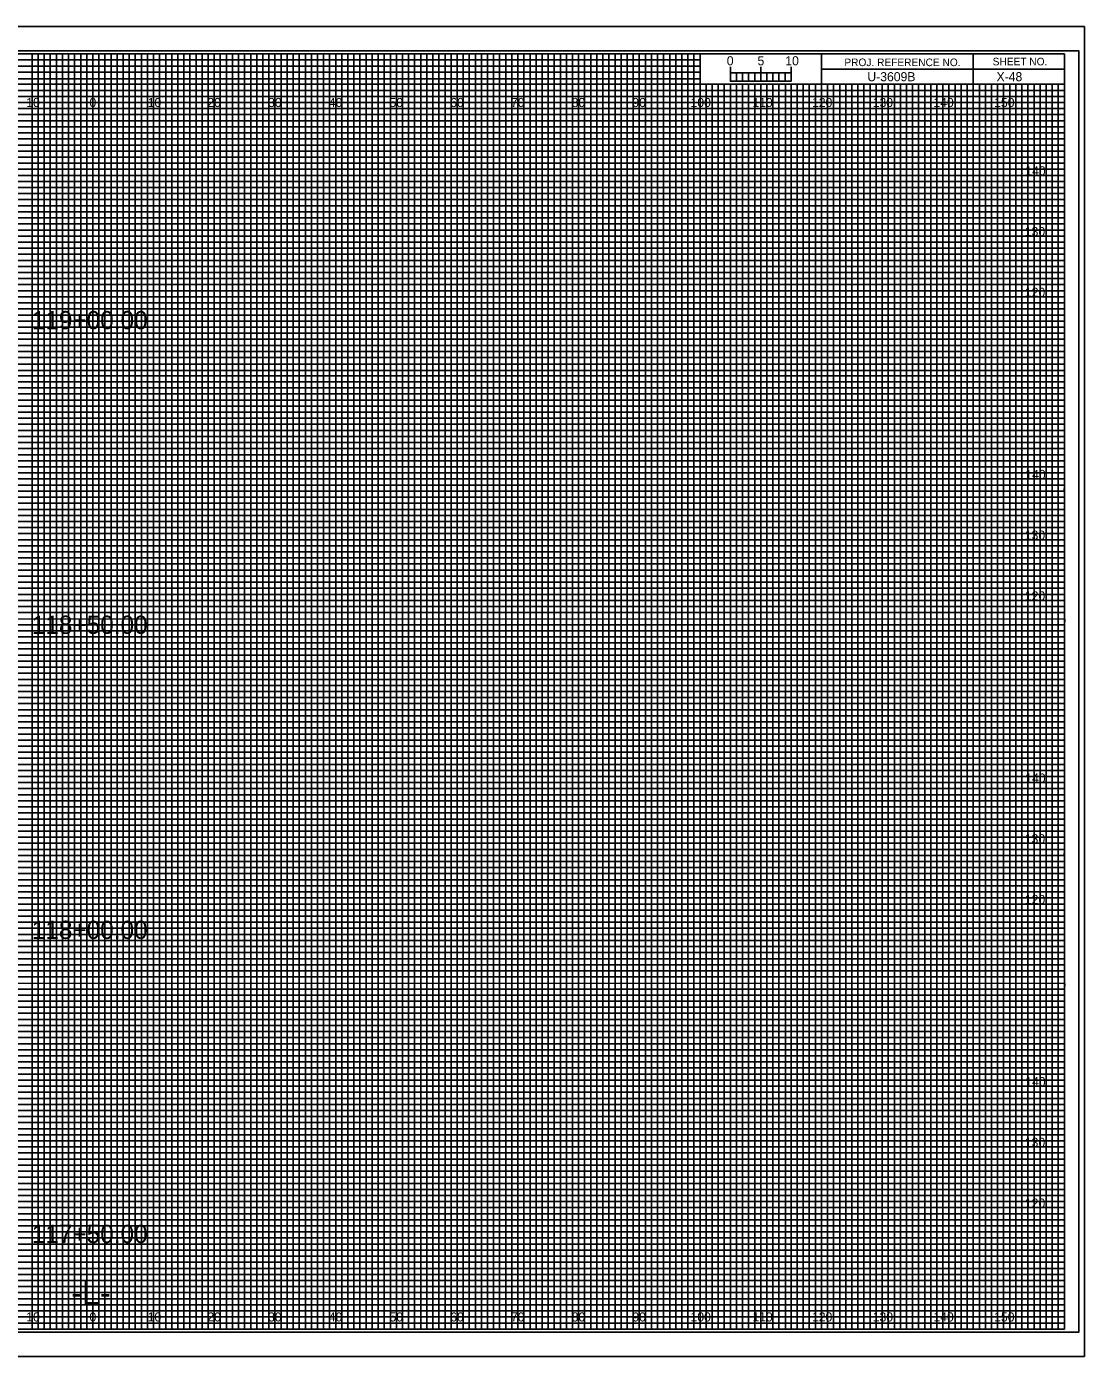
# Model space of a CAD drawing. Extents: x -13 to 329, y -17 to 10994.
# Drawn here: x 149.1 to 323.3, y 10115.5 to 10334.5 of the extents above; entities that cross this region are included whole.
import ezdxf

# ---------------------------------------------------------------- set-up
doc = ezdxf.new("R2010")
doc.units = 0
for name, color, linetype in [('Prop XS Alignment Label', 7, 'Continuous'), ('Prop XS Bar Scale Labels', 7, 'Continuous'), ('Prop XS Elevation Labels', 7, 'Continuous'), ('Prop XS Offset Labels', 7, 'Continuous'), ('Prop XS Project Number', 7, 'Continuous'), ('Prop XS Sheet Number', 7, 'Continuous'), ('Prop XS Station Labels', 7, 'Continuous'), ('Sheet Cross Section CELL', 7, 'Continuous'), ('Sheet Cross Section Grid Major CELL', 7, 'Continuous'), ('Sheet Cross Section Grid Middle CELL', 7, 'Continuous'), ('Sheet Cross Section Grid Minor 1 CELL', 7, 'Continuous'), ('Sheet Cross Section Grid Minor 2 CELL', 7, 'Continuous'), ('Sheet Cross Section Scale CELL', 7, 'Continuous'), ('Sheet Cutting Line CELL', 7, 'Continuous'), ('Sheet DOT Grid CELL', 7, 'Continuous'), ('Sheet Plot Border Inside CELL', 7, 'Continuous'), ('Sheet Plot Border Outside CELL', 7, 'Continuous')]:
    doc.layers.add(name, color=color, linetype=linetype)

msp = doc.modelspace()

# ---------------------------------------------------------------- linework, layer by layer
at = {"layer": 'Sheet Cross Section CELL'}
for p, q in [((305, 10330), (305, 10325)), ((305, 10325), (305, 10330)), ((280, 10327.5), (280, 10325)), ((320, 10327.49), (280, 10327.49)), ((280, 10325), (320, 10325))]:
    msp.add_line(p, q, dxfattribs=at)
for points in [[(320, 10330), (0, 10330), (0, 10120), (320, 10120)], [(280, 10330), (260, 10330), (260, 10325.03), (280, 10325.03)], [(320, 10330), (280, 10330), (280, 10325), (320, 10325)]]:
    msp.add_lwpolyline(points, close=True, dxfattribs=at)
at = {"layer": 'Sheet Cross Section Grid Major CELL'}
for p, q in [((150, 10330), (140, 10330)), ((150, 10120), (150, 10330)), ((170, 10330), (160, 10330)), ((160, 10330), (160, 10120)), ((170, 10120), (170, 10330)), ((190, 10330), (180, 10330)), ((180, 10330), (180, 10120)), ((190, 10120), (190, 10330)), ((210, 10330), (200, 10330)), ((200, 10330), (200, 10120)), ((210, 10120), (210, 10330)), ((230, 10330), (220, 10330)), ((220, 10330), (220, 10120)), ((230, 10120), (230, 10330)), ((250, 10330), (240, 10330)), ((240, 10330), (240, 10120)), ((250, 10120), (250, 10330)), ((260, 10330), (260, 10120)), ((270, 10120), (270, 10325)), ((290, 10325), (280, 10325)), ((280, 10325), (280, 10120)), ((290, 10120), (290, 10325)), ((310, 10325), (300, 10325)), ((300, 10325), (300, 10120)), ((310, 10120), (310, 10325)), ((160, 10120), (150, 10120)), ((180, 10120), (170, 10120)), ((200, 10120), (190, 10120)), ((220, 10120), (210, 10120)), ((240, 10120), (230, 10120)), ((260, 10120), (250, 10120)), ((280, 10120), (270, 10120)), ((300, 10120), (290, 10120)), ((320, 10120), (310, 10120)), ((320, 10120), (320, 10120))]:
    msp.add_line(p, q, dxfattribs=at)
for points in [[(0, 10320), (320, 10320), (320, 10310), (0, 10310)], [(0, 10300), (320, 10300), (320, 10290), (0, 10290)], [(0, 10280), (320, 10280), (320, 10270), (0, 10270)], [(0, 10260), (320, 10260), (320, 10250), (0, 10250)], [(0, 10240), (320, 10240), (320, 10230), (0, 10230)], [(0, 10220), (320, 10220), (320, 10210), (0, 10210)], [(0, 10200), (320, 10200), (320, 10190), (0, 10190)], [(0, 10180), (320, 10180), (320, 10170), (0, 10170)], [(0, 10160), (320, 10160), (320, 10150), (0, 10150)], [(0, 10140), (320, 10140), (320, 10130), (0, 10130)]]:
    msp.add_lwpolyline(points, dxfattribs=at)
at = {"layer": 'Sheet Cross Section Grid Middle CELL'}
for points in [[(145, 10120), (155, 10120), (155, 10330), (165, 10330), (165, 10120), (175, 10120), (175, 10330), (185, 10330), (185, 10120), (195, 10120), (195, 10330), (205, 10330), (205, 10120), (215, 10120), (215, 10330), (225, 10330), (225, 10120), (235, 10120), (235, 10330), (245, 10330), (245, 10120), (255, 10120), (255, 10330), (259.93, 10330), (260, 10330), (260, 10325), (264.99, 10325), (264.99, 10120), (275, 10120), (275, 10325), (285, 10325), (285, 10120), (295, 10120), (295, 10325), (305, 10325), (305, 10120), (315, 10120), (315, 10325)], [(0, 10325), (275, 10325)], [(0, 10305), (320, 10305), (320, 10315), (0, 10315)], [(0, 10285), (320, 10285), (320, 10295), (0, 10295)], [(0, 10265), (320, 10265), (320, 10275), (0, 10275)], [(0, 10245), (320, 10245), (320, 10255), (0, 10255)], [(0, 10225), (320, 10225), (320, 10235), (0, 10235)], [(0, 10205), (320, 10205), (320, 10215), (0, 10215)], [(0, 10185), (320, 10185), (320, 10195), (0, 10195)], [(0, 10165), (320, 10165), (320, 10175), (0, 10175)], [(0, 10145), (320, 10145), (320, 10155), (0, 10155)], [(0, 10125), (320, 10125), (320, 10135), (0, 10135)]]:
    msp.add_lwpolyline(points, dxfattribs=at)
at = {"layer": 'Sheet Cross Section Grid Minor 1 CELL'}
for p, q in [((0, 10329), (260, 10329)), ((260, 10329), (260, 10327.98)), ((260, 10327.98), (0, 10327.98)), ((0, 10327), (260, 10327)), ((260, 10325.89), (0, 10325.89)), ((260, 10327), (260, 10325.89)), ((0, 10324), (320, 10324))]:
    msp.add_line(p, q, dxfattribs=at)
for points in [[(0, 10323), (270, 10323), (320, 10323), (320, 10322), (0, 10322)], [(0, 10321), (320, 10321), (320, 10319), (0, 10319)], [(0, 10318), (320, 10318), (320, 10317), (0, 10316.98)], [(0, 10316), (320, 10316), (320, 10314), (0, 10314)], [(0, 10313), (320, 10313), (320, 10312), (0, 10312)], [(0, 10311), (320, 10311), (320, 10309), (0, 10309)], [(0, 10308), (320, 10308), (320, 10307), (0, 10307)], [(0, 10306), (320, 10306), (320, 10304), (0, 10304)], [(0, 10303), (320, 10303), (320, 10302), (0, 10302)], [(0, 10301), (320, 10301), (320, 10299), (0, 10299)], [(0, 10298), (320, 10298), (320, 10297), (0, 10297)], [(0, 10296), (320, 10296), (320, 10293.95), (320, 10293), (320, 10292), (0, 10292)], [(0, 10294), (320, 10294), (320, 10293), (0, 10293)], [(0, 10291), (320, 10291), (320, 10289), (0, 10289.03)], [(0, 10289.03), (320, 10289), (320, 10288), (0, 10288)], [(0, 10287), (320, 10287), (320, 10286), (0, 10286)], [(0, 10284), (320, 10284), (320, 10283), (0, 10283)], [(0, 10282), (320, 10282), (320, 10281), (0, 10281)], [(-0.07, 10278.89), (320, 10278.89), (320, 10277.88), (-0.07, 10277.88)], [(0, 10277), (320, 10277), (320, 10276), (0, 10276)], [(0, 10274), (320, 10274), (320, 10273), (0, 10273)], [(0, 10272), (320, 10272), (320, 10271), (0, 10271)], [(0, 10269), (320, 10269), (320, 10268), (0, 10268)], [(0, 10267), (320, 10267), (320, 10266), (0, 10266)], [(0, 10264), (320, 10264), (320, 10263), (0, 10263)], [(0, 10262), (320, 10262), (320, 10261), (0, 10261)], [(0, 10259), (320, 10259), (319.99, 10257.98), (0, 10258)], [(0, 10257), (320, 10257), (320, 10256), (0, 10256)], [(0, 10254), (320, 10254), (320, 10253), (0, 10253)], [(0, 10252), (320, 10252), (320, 10251), (0, 10251)], [(0, 10249), (320, 10249), (320, 10248), (0, 10248)], [(0, 10247), (320, 10247), (320, 10246), (0, 10246)], [(0, 10244), (320, 10244), (320, 10243), (0, 10243)], [(0, 10242), (320, 10242), (320, 10241), (0, 10241)], [(0, 10239), (320, 10239), (320, 10238), (0, 10238)], [(0, 10236.99), (320.07, 10236.91), (320, 10236), (0, 10236)], [(0, 10234), (320, 10234), (320, 10233), (0, 10233)], [(0, 10232), (320, 10232), (320, 10231), (0, 10231)], [(0, 10229), (320, 10229), (320, 10228), (0, 10228)], [(0, 10227), (320, 10227), (320, 10226), (0, 10226)], [(0, 10224), (320, 10224), (320, 10223), (0, 10223)], [(0, 10222), (320, 10222), (320, 10221), (0, 10221)], [(0, 10219), (320, 10219), (320, 10218), (0, 10218)], [(0, 10217), (320, 10217), (320, 10216), (0, 10216)], [(0, 10214), (320, 10214), (320, 10213), (0, 10213)], [(0, 10212), (320, 10212), (320, 10211), (0, 10211)], [(0, 10209), (320, 10209), (320, 10208), (0, 10208)], [(0, 10207), (320, 10207), (320, 10206), (0, 10206)], [(0, 10204), (320, 10204), (320, 10203), (0, 10203)], [(0, 10202), (320, 10202), (320, 10201), (0, 10201)], [(0, 10199), (320, 10199), (319.99, 10197.98), (0, 10198)], [(0, 10197), (320, 10197), (320, 10196), (0, 10196)], [(0, 10194), (320, 10194), (320, 10193), (0, 10193)], [(0, 10192), (320, 10192), (320, 10191), (0, 10191)], [(0, 10189), (320, 10189), (320, 10188), (0, 10188)], [(0, 10187), (320, 10187), (320, 10186), (0, 10186)], [(0, 10184), (320, 10184), (320, 10183), (0, 10183)], [(0, 10182), (320, 10182), (320, 10181), (0, 10181)], [(0, 10179), (320, 10179), (320, 10178), (0, 10178)], [(0, 10176.99), (320.07, 10176.91), (320, 10176), (0, 10176)], [(0, 10174), (320, 10174), (320, 10173), (0, 10173)], [(0, 10172), (320, 10172), (320, 10171), (0, 10171)], [(0, 10169), (320, 10169), (320, 10168), (0, 10168)], [(0, 10167), (320, 10167), (320, 10166), (0, 10166)], [(0, 10164), (320, 10164), (320, 10163), (0, 10163)], [(0, 10162), (320, 10162), (320, 10161), (0, 10161)], [(0, 10159), (320, 10159), (320, 10158), (0, 10158)], [(0, 10157), (320, 10157), (320, 10156), (0, 10156)], [(0, 10154), (320, 10154), (320, 10153), (0, 10153)], [(0, 10152), (320, 10152), (320, 10151), (0, 10151)], [(0, 10149), (320, 10149), (320, 10148), (0, 10148)], [(0, 10147), (320, 10147), (320, 10146), (0, 10146)], [(0, 10144), (320, 10144), (320, 10143), (0, 10143)], [(0, 10142), (320, 10142), (320, 10141), (0, 10141)], [(0, 10139), (320, 10139), (320, 10138), (0, 10138)], [(0, 10137), (320, 10137), (320, 10136), (0, 10136)], [(0, 10134), (320, 10134), (320, 10133), (0, 10133)], [(0, 10132), (320, 10132), (320, 10131), (0, 10131)], [(0, 10129), (320, 10129), (320, 10128), (0, 10128)], [(0, 10127), (320, 10127), (320, 10126), (0, 10126)], [(0, 10124), (320, 10124), (320, 10123), (0, 10123)], [(0, 10122), (320, 10122), (320, 10121), (0, 10121)]]:
    msp.add_lwpolyline(points, dxfattribs=at)
at = {"layer": 'Sheet Cross Section Grid Minor 2 CELL'}
for p, q in [((267, 10325), (266.01, 10325)), ((266.01, 10325), (266.01, 10120)), ((267, 10120), (267, 10325)), ((269, 10325), (268, 10325)), ((268, 10325), (268, 10120)), ((269, 10120), (269, 10325)), ((266.01, 10120), (265, 10120)), ((268, 10120), (267, 10120))]:
    msp.add_line(p, q, dxfattribs=at)
for points in [[(150, 10120), (151, 10120), (151, 10330), (152, 10330), (152, 10120)], [(152, 10120), (153, 10120), (153, 10330), (154, 10330), (154, 10120)], [(155, 10120), (156, 10120), (156, 10330), (157, 10330), (157, 10120)], [(157, 10120), (158, 10120), (158, 10330), (159, 10330), (159, 10120)], [(160, 10120), (161, 10120), (161, 10330), (162, 10330), (162, 10120)], [(162, 10120), (163, 10120), (163, 10330), (164, 10330), (164, 10120)], [(165, 10120), (166, 10120), (166, 10330), (167, 10330), (167, 10120)], [(167, 10120), (168, 10120), (168, 10330), (169, 10330), (169, 10120)], [(170, 10120), (171, 10120), (171, 10330), (172, 10330), (172, 10120)], [(172, 10120), (173, 10120), (173, 10330), (174, 10330), (174, 10120)], [(175, 10120), (176, 10120), (176, 10330), (177, 10330), (177, 10120)], [(177, 10120), (178, 10120), (178, 10330), (179, 10330), (179, 10120)], [(180, 10120), (181, 10120), (181, 10330), (182, 10330), (182, 10120)], [(182, 10120), (183, 10120), (183, 10330), (184, 10330), (184, 10120)], [(185, 10120), (186, 10120), (186, 10330), (187, 10330), (187, 10120)], [(187, 10120), (188, 10120), (188, 10330), (189, 10330), (189, 10120)], [(190, 10120), (191, 10120), (191, 10330), (192, 10330), (192, 10120)], [(192, 10120), (193, 10120), (193, 10330), (194, 10330), (194, 10120)], [(195, 10120), (196, 10120), (196, 10330), (197, 10330), (197, 10120)], [(197, 10120), (198, 10120), (198, 10330), (199, 10330), (199, 10120)], [(200, 10120), (201, 10120), (201, 10330), (202, 10330), (202, 10120)], [(202, 10120), (203, 10120), (203, 10330), (204, 10330), (204, 10120)], [(205, 10120), (206, 10120), (206, 10330), (207, 10330), (207, 10120)], [(207, 10120), (208, 10120), (208, 10330), (209, 10330), (209, 10120)], [(210, 10120), (211, 10120), (211, 10330), (212, 10330), (212, 10120)], [(212, 10120), (213, 10120), (213, 10330), (214, 10330), (214, 10120)], [(215, 10120), (216, 10120), (216, 10330), (217, 10330), (217, 10120)], [(217, 10120), (218, 10120), (218, 10330), (219, 10330), (219, 10120)], [(220, 10120), (221, 10120), (221, 10330), (222, 10330), (222, 10120)], [(222, 10120), (223, 10120), (223, 10330), (224, 10330), (224, 10120)], [(225, 10120), (226, 10120), (226, 10330), (227, 10330), (227, 10120)], [(227, 10120), (228, 10120), (228, 10330), (229, 10330), (229, 10120)], [(230, 10120), (231, 10120), (231, 10330), (232, 10330), (232, 10120)], [(232, 10120), (233, 10120), (233, 10330), (234, 10330), (234, 10120)], [(235, 10120), (236, 10120), (236, 10330), (237, 10330), (237, 10120)], [(237, 10120), (238, 10120), (238, 10330), (239, 10330), (239, 10120)], [(240, 10120), (241, 10120), (241, 10330), (242, 10330), (242, 10120)], [(242, 10120), (243, 10120), (243, 10330), (244, 10330), (244, 10120)], [(245, 10120), (246, 10120), (246, 10330), (247, 10330), (247, 10120)], [(247, 10120), (248, 10120), (248, 10330), (249, 10330), (249, 10120)], [(250, 10120), (251, 10120), (251, 10330), (252, 10330), (252, 10120)], [(252, 10120), (253, 10120), (253, 10330), (254, 10330), (254, 10120)], [(255, 10120), (256, 10120), (256, 10330), (257, 10330), (257, 10120)], [(257, 10120), (258, 10120), (258, 10330), (259, 10330), (259, 10120)], [(260, 10120), (261, 10120), (261, 10325), (262.02, 10325), (262.02, 10120)], [(262, 10120), (263, 10120), (263, 10325), (263.99, 10325), (263.99, 10120)], [(270, 10120), (270.98, 10120), (270.98, 10325), (272, 10325), (272, 10120)], [(272, 10120), (273, 10120), (273, 10325), (274.05, 10325), (274.05, 10120)], [(275, 10120), (276, 10120), (276, 10325), (277, 10325), (277, 10120)], [(277, 10120), (278, 10120), (278, 10325), (279, 10325), (279, 10120)], [(280, 10120), (281, 10120), (281, 10325), (282, 10325), (282, 10120)], [(282, 10120), (283, 10120), (283, 10325), (284, 10325), (284, 10120)], [(285, 10120), (286, 10120), (286, 10325), (287, 10325), (287, 10120)], [(287, 10120), (288, 10120), (288, 10325), (289, 10325), (289, 10120)], [(290, 10120), (291, 10120), (291, 10325), (292, 10325), (292, 10120)], [(292, 10120), (293, 10120), (293, 10325), (294, 10325), (294, 10120)], [(295, 10120), (296, 10120), (296, 10325), (297, 10325), (297, 10120)], [(297, 10120), (298, 10120), (298, 10325), (299, 10325), (299, 10120)], [(300, 10120), (301, 10120), (301, 10325), (302, 10325), (302, 10120)], [(302, 10120), (303, 10120), (303, 10325), (304, 10325), (304, 10120)], [(305, 10120), (306, 10120), (306, 10325), (307, 10325), (307, 10120)], [(307, 10120), (308, 10120), (308, 10325), (309, 10325), (309, 10120)], [(310, 10120), (311, 10120), (311, 10325), (312, 10325), (312, 10120)], [(312, 10120), (313, 10120), (313, 10325), (314, 10325), (314, 10120)], [(315, 10120), (316, 10120), (316, 10325), (317, 10325), (317, 10120)], [(317, 10120), (318, 10120), (318, 10325), (319, 10325), (319, 10120)]]:
    msp.add_lwpolyline(points, dxfattribs=at)
at = {"layer": 'Sheet Cross Section Scale CELL'}
for p, q in [((265, 10325.49), (265, 10327.9)), ((265, 10326.9), (265, 10327.9)), ((270, 10325.49), (270, 10327.9)), ((275, 10325.49), (275, 10327.9)), ((275, 10326.9), (275, 10327.9))]:
    msp.add_line(p, q, dxfattribs=at)
for points in [[(275, 10326.9), (265, 10326.9), (265, 10325.49), (275, 10325.49)], [(265, 10326.9), (266, 10326.9), (266, 10325.49), (265, 10325.49)], [(267, 10326.9), (268, 10326.9), (268, 10325.49), (267, 10325.49)], [(269, 10326.9), (270, 10326.9), (270, 10325.49), (269, 10325.49)], [(271, 10326.9), (272, 10326.9), (272, 10325.49), (271, 10325.49)], [(273, 10326.9), (274, 10326.9), (274, 10325.49), (273, 10325.49)]]:
    msp.add_lwpolyline(points, close=True, dxfattribs=at)
at = {"layer": 'Sheet Cutting Line CELL'}
for p, q in [((323.3, 10334.5), (-13.4, 10334.5)), ((-13.4, 10115.5), (323.3, 10115.5))]:
    msp.add_line(p, q, dxfattribs=at)
at = {"layer": 'Sheet DOT Grid CELL'}
for p, q in [((150, 10120), (150, 10330)), ((160, 10120), (160, 10330)), ((170, 10120), (170, 10330)), ((180, 10120), (180, 10330)), ((190, 10120), (190, 10330)), ((200, 10120), (200, 10330)), ((210, 10120), (210, 10330)), ((220, 10120), (220, 10330)), ((230, 10120), (230, 10330)), ((240, 10120), (240, 10330)), ((250, 10120), (250, 10330)), ((260, 10120), (260, 10324.69)), ((270, 10120), (270, 10324.69)), ((280, 10120), (280, 10324.69)), ((290, 10120), (290, 10324.69)), ((300, 10120), (300, 10324.69)), ((310, 10120), (310, 10324.69)), ((0, 10320), (320, 10320)), ((0, 10310), (320, 10310)), ((0, 10300), (320, 10300)), ((0, 10290), (320, 10290)), ((0, 10280), (320, 10280)), ((0, 10270), (320, 10270)), ((0, 10260), (320, 10260)), ((0, 10250), (320, 10250)), ((0, 10240), (320, 10240)), ((0, 10230), (320, 10230)), ((0, 10220), (320, 10220)), ((0, 10210), (320, 10210)), ((0, 10200), (320, 10200)), ((0, 10190), (320, 10190)), ((0, 10180), (320, 10180)), ((0, 10170), (320, 10170)), ((0, 10160), (320, 10160)), ((0, 10150), (320, 10150)), ((0, 10140), (320, 10140)), ((0, 10130), (320, 10130))]:
    msp.add_line(p, q, dxfattribs=at)
at = {"layer": 'Sheet Plot Border Inside CELL'}
msp.add_lwpolyline([(-10.8, 10119.5), (322.4, 10119.5), (322.4, 10330.5), (-10.8, 10330.5)], close=True, dxfattribs=at)
at = {"layer": 'Sheet Plot Border Outside CELL'}
msp.add_lwpolyline([(-13.4, 10115.5), (323.3, 10115.5), (323.3, 10334.5), (-13.4, 10334.5)], close=True, dxfattribs=at)

# ---------------------------------------------------------------- texts
at = {"layer": 'Prop XS Alignment Label'}
msp.add_text('-L-', height=4, dxfattribs=at).set_placement((156.42, 10124))
at = {"layer": 'Prop XS Bar Scale Labels'}
for s, p in [('5', (269.47, 10328.12)), ('10', (274.04, 10328.12))]:
    msp.add_text(s, height=1.5, dxfattribs=at).set_placement(p)
at = {"layer": 'Prop XS Elevation Labels'}
for s, p in [('140', (313.57, 10310)), ('130', (313.49, 10300)), ('120', (313.5, 10290)), ('140', (313.57, 10260)), ('130', (313.49, 10250)), ('120', (313.5, 10240)), ('140', (313.57, 10210)), ('130', (313.49, 10200)), ('120', (313.5, 10190)), ('140', (313.57, 10160)), ('130', (313.49, 10150)), ('120', (313.5, 10140))]:
    msp.add_text(s, height=1.5, dxfattribs=at).set_placement(p)
at = {"layer": 'Prop XS Offset Labels'}
for s, p in [('10', (149.04, 10321.25)), ('0', (159.45, 10321.25)), ('0', (159.45, 10321.25)), ('10', (169.04, 10321.25)), ('20', (178.86, 10321.25)), ('30', (188.86, 10321.25)), ('40', (198.86, 10321.25)), ('50', (208.86, 10321.25)), ('60', (218.86, 10321.25)), ('70', (228.86, 10321.25)), ('80', (238.86, 10321.25)), ('90', (248.86, 10321.25)), ('100', (258.44, 10321.25)), ('110', (268.62, 10321.25)), ('120', (278.44, 10321.25)), ('130', (288.44, 10321.25)), ('140', (298.44, 10321.25)), ('150', (308.44, 10321.25)), ('10', (149.04, 10121.25)), ('0', (159.45, 10121.25)), ('0', (159.45, 10121.25)), ('10', (169.04, 10121.25)), ('20', (178.86, 10121.25)), ('30', (188.86, 10121.25)), ('40', (198.86, 10121.25)), ('50', (208.86, 10121.25)), ('60', (218.86, 10121.25)), ('70', (228.86, 10121.25)), ('80', (238.86, 10121.25)), ('90', (248.86, 10121.25)), ('100', (258.44, 10121.25)), ('110', (268.62, 10121.25)), ('120', (278.44, 10121.25)), ('130', (288.44, 10121.25)), ('140', (298.44, 10121.25)), ('150', (308.44, 10121.25))]:
    msp.add_text(s, height=1.5, dxfattribs=at).set_placement(p)
at = {"layer": 'Prop XS Project Number'}
msp.add_text('U-3609B', height=1.5, dxfattribs=at).set_placement((287.56, 10325.5))
at = {"layer": 'Prop XS Sheet Number'}
msp.add_text('X-48', height=1.5, dxfattribs=at).set_placement((308.83, 10325.5))
at = {"layer": 'Prop XS Station Labels'}
for s, p in [('119+00.00', (149.95, 10284.66)), ('118+50.00', (149.95, 10234.49)), ('118+00.00', (149.95, 10184.25)), ('117+50.00', (149.95, 10134.17))]:
    msp.add_text(s, height=3, dxfattribs=at).set_placement(p)
at = {"layer": 'Sheet Cross Section CELL'}
for s, p in [('PROJ. REFERENCE NO.', (283.77, 10327.99)), ('SHEET NO.', (308.19, 10328.12))]:
    msp.add_text(s, height=1.25, dxfattribs=at).set_placement(p)
at = {"layer": 'Sheet Cross Section Scale CELL'}
msp.add_text('0', height=1.5, dxfattribs=at).set_placement((264.41, 10328.12))

doc.saveas('drawing.dxf')
